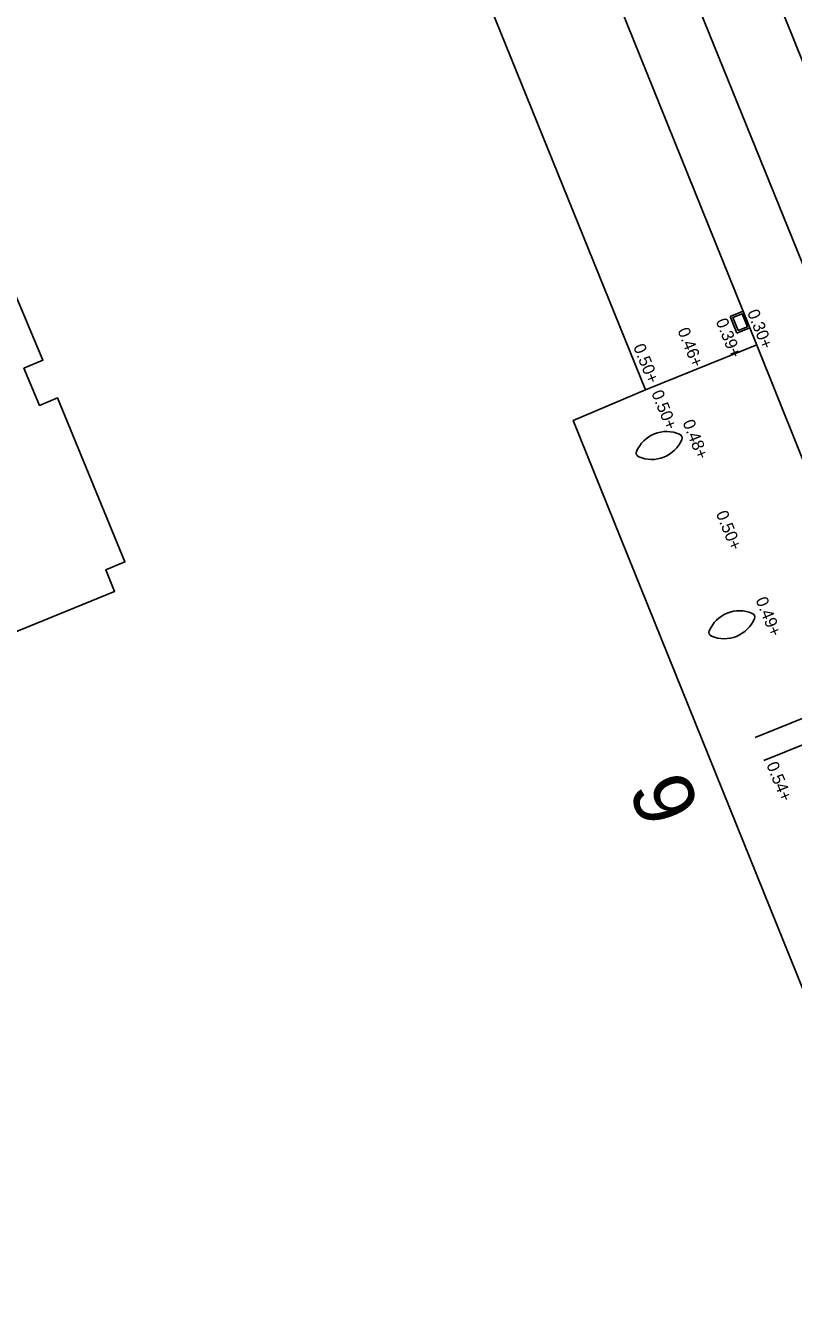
# Model space of a CAD drawing. Extents: x 122462 to 123306, y 485548 to 486417.
# Drawn here: x 122942.64 to 122961.7, y 485721.73 to 485753.45 of the extents above; entities that cross this region are included whole.
import ezdxf

# ---------------------------------------------------------------- set-up
doc = ezdxf.new("R2010")
doc.units = 0
for name, color, linetype in [('B-WE-OG-HOOGTEPUNT-S', 7, 'Continuous'), ('B-WE-OG-TOPOGRAFIE_BEBOUWING-G', 7, 'Continuous'), ('B-WE-OG-TOPOKAART-G', 7, 'Continuous'), ('B-WE-RI-HWA_KOLK-S', 7, 'Continuous'), ('B-WE-VH-KANTOPSLUITING_OPSLUITBAND_100X200-G', 7, 'Continuous'), ('B-WE-VH-KANTOPSLUITING_TROTTOIRBAND_130 150-G', 7, 'Continuous'), ('B-WE-VH-KANTOPSLUITING_TROTTOIRBAND_180 200-G', 7, 'Continuous'), ('B-WE-VH-MATERIAALGRENS-G', 7, 'Continuous'), ('Level 1', 7, 'Continuous'), ('Level 58', 7, 'Continuous')]:
    doc.layers.add(name, color=color, linetype=linetype)

msp = doc.modelspace()

# ---------------------------------------------------------------- linework, layer by layer
at = {"layer": 'B-WE-OG-TOPOGRAFIE_BEBOUWING-G'}
for centre, radius, start, end in [((122958.556, 485742.564), 0.81, 66.6668, 157.4433), ((122958.181, 485743.488), 0.81, 246.6668, 337.4433), ((122958.837, 485743.216), 0.1, 337.4433, 66.6668), ((122957.9, 485742.836), 0.1, 157.4433, 246.6668), ((122960.36, 485738.116), 0.81, 66.6668, 157.4433), ((122959.985, 485739.04), 0.81, 246.6668, 337.4433), ((122960.641, 485738.768), 0.1, 337.4433, 66.6668), ((122959.704, 485738.388), 0.1, 157.4433, 246.6668)]:
    msp.add_arc(centre, radius, start, end, dxfattribs=at)
at = {"layer": 'B-WE-OG-TOPOKAART-G'}
msp.add_lwpolyline([(122930.558, 485780.209), (122935.952, 485782.422), (122935.762, 485782.891), (122936.616, 485783.237), (122936.805, 485782.767), (122941.366, 485784.612), (122943.842, 485778.46), (122944.174, 485778.596), (122958.027, 485744.404), (122956.235, 485743.648), (122963.319, 485726.116), (122964.959, 485726.783), (122967.006, 485721.732)], dxfattribs=at)
at = {"layer": 'B-WE-RI-HWA_KOLK-S'}
for p, q in [((122960.13, 485746.231), (122960.454, 485746.363)), ((122960.454, 485746.363), (122960.623, 485745.945)), ((122960.473, 485746.316), (122960.468, 485746.314)), ((122960.298, 485745.814), (122960.13, 485746.231)), ((122960.463, 485746.301), (122960.48, 485746.258)), ((122960.48, 485746.258), (122960.493, 485746.227)), ((122960.51, 485746.223), (122960.506, 485746.222)), ((122960.509, 485746.185), (122960.539, 485746.111)), ((122960.52, 485746.2), (122960.515, 485746.198)), ((122960.557, 485746.108), (122960.552, 485746.106)), ((122960.556, 485746.069), (122960.586, 485745.995)), ((122960.566, 485746.084), (122960.562, 485746.082)), ((122960.623, 485745.945), (122960.298, 485745.814)), ((122960.604, 485745.992), (122960.599, 485745.99))]:
    msp.add_line(p, q, dxfattribs=at)
msp.add_lwpolyline([(122960.326, 485745.879), (122960.195, 485746.204), (122960.426, 485746.297), (122960.558, 485745.973)], close=True, dxfattribs=at)
for centre, start, end in [((122960.472, 485746.305), 112.0015, 202.0015), ((122960.502, 485746.231), 202.0015, 292.0015), ((122960.519, 485746.189), 112.0015, 202.0015), ((122960.549, 485746.115), 202.0015, 292.0015), ((122960.566, 485746.073), 112.0015, 202.0015), ((122960.596, 485745.999), 202.0015, 292.0015)]:
    msp.add_arc(centre, 0.01, start, end, dxfattribs=at)
at = {"layer": 'B-WE-VH-KANTOPSLUITING_OPSLUITBAND_100X200-G'}
msp.add_lwpolyline([(122960.779, 485745.561), (122965.52, 485733.746), (122968.048, 485727.518)], dxfattribs=at)
at = {"layer": 'B-WE-VH-KANTOPSLUITING_TROTTOIRBAND_130 150-G'}
msp.add_lwpolyline([(122944.02, 485787.037), (122960.779, 485745.561)], dxfattribs=at)
at = {"layer": 'B-WE-VH-KANTOPSLUITING_TROTTOIRBAND_180 200-G'}
for points in [[(122962.728, 485745.564), (122954.408, 485766.082), (122945.68, 485787.702)], [(122958.571, 485760.89), (122964.195, 485746.938)]]:
    msp.add_lwpolyline(points, dxfattribs=at)
at = {"layer": 'B-WE-VH-MATERIAALGRENS-G'}
for points in [[(122958.027, 485744.404), (122960.793, 485745.527)], [(122963.359, 485738.794), (122962.814, 485738.575), (122963.496, 485736.888), (122960.755, 485735.777)], [(122960.965, 485735.208), (122963.735, 485736.323), (122964.526, 485734.373), (122965.067, 485734.592)]]:
    msp.add_lwpolyline(points, dxfattribs=at)
at = {"layer": 'Level 1'}
msp.add_lwpolyline([(122939.301, 485754.177), (122941.028, 485750.138), (122940.565, 485749.944), (122940.956, 485749.015), (122941.366, 485749.193), (122943.07, 485745.143), (122942.598, 485744.944), (122942.986, 485744.02), (122943.433, 485744.208), (122945.106, 485740.138), (122944.631, 485739.944), (122944.851, 485739.405), (122935.136, 485735.442)], dxfattribs=at)

# ---------------------------------------------------------------- texts
at = {"layer": 'B-WE-OG-HOOGTEPUNT-S'}
for s, rotation, p in [('0.30+', 292.0439, (122960.546, 485746.333)), ('0.39+', 292.0555, (122959.767, 485746.112)), ('0.46+', 292.0555, (122958.817, 485745.881)), ('0.50+', 292.0555, (122957.717, 485745.479)), ('0.50+', 292.0439, (122958.169, 485744.33)), ('0.48+', 292.0439, (122958.943, 485743.599)), ('0.50+', 292.0439, (122959.771, 485741.339)), ('0.49+', 292.0439, (122960.756, 485739.197)), ('0.54+', 292.0439, (122961.024, 485735.104))]:
    msp.add_text(s, height=0.3, rotation=rotation, dxfattribs=at).set_placement(p)
at = {"layer": 'Level 58'}
msp.add_text('9', height=1.5, rotation=290.5066, dxfattribs=at).set_placement((122957.599, 485734.507))

doc.saveas('drawing.dxf')
